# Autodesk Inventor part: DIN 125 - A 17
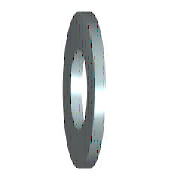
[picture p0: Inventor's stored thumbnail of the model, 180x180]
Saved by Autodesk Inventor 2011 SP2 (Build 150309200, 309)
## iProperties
Created: 2010-02
Part Number: DIN 125 - A 17
Material: Stahl, weich, unlegiert
Description: Unterlegscheibe
Document SubType Name: Modeling
Standard: DIN 125
Designer: JRE
Standards Organization: DIN
Language: de-DE
Size Designation: A 17
Categories: <MemberInstance><Categories><Category DisplayName="Verbindungselemente" InternalName="e4da775c-781d-43d5-af7c-5136215cf5a6" Mnemonic="FSTN"><Category DisplayNam
Density: 1 g/cm^3
IsCustomPart: 0
Author: JRE
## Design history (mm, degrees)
body "Solid1"
sketch "Skizze"
  geometry: C1 r 15 at (0, 0); C2 r 8.5 at (0, 0); 1 further point
  constraints: 2 centre point, 2 coincident
  dimensions: "d0" = 17 diameter of C2 (= SD1); "d1" = 30 diameter of C1 (= SD2)
extrude "Körper" new body sketch "Skizze" distance "d2" = 3 (= SD); taper "d3" = 0 deg
workaxis "Work Axis1"
workplane "Work Plane1"
other parameters: "SD1" = 17 [user parameter; used in 1 equation term], "SD2" = 30 [user parameter; used in 1 equation term], "SD" = 3 [user parameter; used in 1 equation term], "d4" = 0, "d5" = 0, "d6" = 0, "d7" = 0, "NND" = 16 [user parameter]
